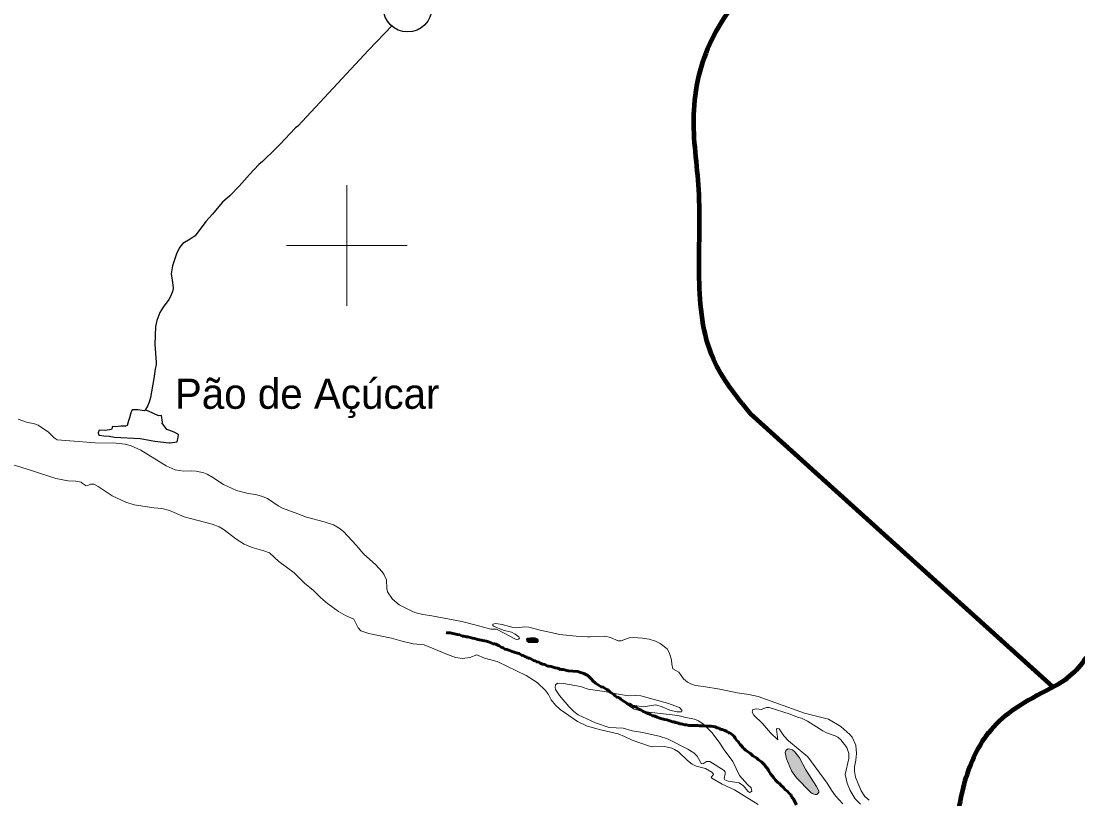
# Model space of a CAD drawing. Extents: x -1643653 to 4543381, y 1624270 to 13878484.
# Drawn here: x 669599 to 687117, y 8915829 to 8928718 of the extents above; entities that cross this region are included whole.
import ezdxf

# ---------------------------------------------------------------- set-up
doc = ezdxf.new("R2010")
doc.units = 0
doc.header["$LTSCALE"] = 200
doc.linetypes.add('LONG_DASH_SHORT_DASH', pattern=[9.9, 6, -1.2, 1.5, -1.2])
for name, color, linetype, lineweight in [('12', 7, 'Continuous', 25), ('2', 7, 'Continuous', 13), ('21', 7, 'Continuous', 25), ('23', 7, 'Continuous', 13), ('25', 7, 'Continuous', 13), ('48', 7, 'Continuous', 25), ('60', 7, 'Continuous', 13), ('7', 7, 'LONG_DASH_SHORT_DASH', 60), ('9', 7, 'Continuous', 90)]:
    doc.layers.add(name, color=color, linetype=linetype, lineweight=lineweight)
doc.layers.add('41', color=7, linetype='Continuous')

msp = doc.modelspace()

# ---------------------------------------------------------------- hatches: boundary and pattern name
at = {"layer": '25'}
for points in [[(678121.8, 8918499.9), (678099.7, 8918499.9), (678072.1, 8918499.9), (678038.9, 8918499.9), (677994.7, 8918494.3), (677978.1, 8918477.8), (677983.7, 8918444.6), (678016.8, 8918422.5), (678066.5, 8918422.5), (678116.3, 8918422.5), (678155, 8918422.5), (678171.5, 8918439.1), (678171.5, 8918466.7), (678155, 8918483.3)], [(682604.9, 8916312), (682500, 8916511.3), (682424.9, 8916610.1), (682387.8, 8916643), (682346.5, 8916655.7), (682313.7, 8916655.9), (682284.1, 8916639.2), (682267.8, 8916618.9), (682264.6, 8916598.1), (682286.2, 8916495.1), (682370.8, 8916295.4), (682452, 8916180.6), (682682.3, 8915939.4), (682710.5, 8915920.7), (682762.8, 8915903.1), (682787.5, 8915903.3), (682820.9, 8915934.7), (682822.2, 8915960.7), (682782.3, 8916035.7)]]:
    msp.add_hatch(color=256, dxfattribs=at).paths.add_polyline_path(points)

# ---------------------------------------------------------------- linework, layer by layer
at = {"layer": '12'}
for points in [[(675747.8, 8928644.7), (675357.8, 8928239.4), (674183.6, 8926978.8), (674145.1, 8926947.6), (673889.8, 8926674.1), (673817.5, 8926604.1)], [(673817.5, 8926604.1), (673601, 8926394.6), (673540.7, 8926341.3), (673385.9, 8926177.5), (673220, 8925987.8), (673060.2, 8925824.4), (672938.9, 8925717.3), (672905.6, 8925678)], [(672905.6, 8925678), (672769.2, 8925517), (672663.1, 8925399.6), (672486.7, 8925159.8), (672402.7, 8925104), (672277.3, 8925032.8), (672246.2, 8924995.7), (672220.2, 8924955.3), (672176.2, 8924860.7)], [(672176.2, 8924860.7), (672161.6, 8924829.2), (672110.6, 8924662), (672086.1, 8924531.1), (672095.5, 8924466.4)], [(672095.5, 8924466.4), (672118.8, 8924306.3), (672118.5, 8924278.5), (672104, 8924223.3), (672070.6, 8924145.4), (672047.1, 8924105), (671951.4, 8923978.3), (671897.8, 8923887.3), (671849.3, 8923755.3), (671827.1, 8923657.7), (671813, 8923357.8), (671840.2, 8923069), (671838.2, 8923027.3), (671822.3, 8922948), (671796.6, 8922795.7)], [(671796.6, 8922795.7), (671743.5, 8922481.6), (671721, 8922405.8), (671692.6, 8922335.7), (671657.6, 8922270.9)]]:
    msp.add_lwpolyline(points, dxfattribs=at)
at = {"layer": '2'}
for p, q in [((675000, 8924000), (675000, 8926000)), ((674000, 8925000), (676000, 8925000))]:
    msp.add_line(p, q, dxfattribs=at)
at = {"layer": '21'}
msp.add_lwpolyline([(672070.8, 8921729.3), (672183.6, 8921744.1), (672204.3, 8921823.7), (672205.8, 8921869.8), (672137.9, 8921906.6), (672045.5, 8921936.8), (672015.8, 8921950.8), (671951.1, 8922034), (671936.7, 8922041.8), (671940.3, 8922071), (671928.8, 8922182.7), (671874.6, 8922176.6), (671712.4, 8922251.7), (671659.2, 8922270.3), (671636.6, 8922261.5), (671534.1, 8922275.4), (671438.6, 8922277.6), (671419.5, 8922227.5), (671398.3, 8922143), (671378.3, 8922092.9), (671356.9, 8922015.4), (671328.1, 8922006.3), (671250.4, 8922007.9), (671162.4, 8921997.4), (671116.6, 8922002), (671109.5, 8921989.5), (671105, 8921961.4), (671096.8, 8921948), (670990.1, 8921931.4), (670891.9, 8921937.6), (670878.8, 8921896.3), (670882.6, 8921866.1), (670900, 8921857.8), (670970.5, 8921845.4), (671059.8, 8921839.3), (671147.8, 8921823.2), (671572.8, 8921799.1), (671817.6, 8921756.7), (672050.9, 8921730.4)], close=True, dxfattribs=at)
at = {"layer": '23'}
for points in [[(674185.8, 8920553), (673931.7, 8920649.3), (673860.5, 8920685.6), (673683.5, 8920804.3), (673583.2, 8920848.3), (673485, 8920874.1), (673363.4, 8920887.3), (673169, 8920938.3), (672954.4, 8921040.4), (672776.3, 8921157.4), (672681.9, 8921209.8), (672626.2, 8921231.8), (672503.5, 8921262.1), (672419, 8921266.9), (672299, 8921260.5), (672150.9, 8921284.8), (672004.6, 8921350.8), (671582.7, 8921606.9), (671424.1, 8921682), (671321.6, 8921707.8), (671173.4, 8921726.6), (670825.1, 8921729), (670198.9, 8921779.1), (670147.5, 8921810.8), (670051.3, 8921908.8), (669880.3, 8922022.2), (669805.2, 8922048.5), (669703.5, 8922065.4), (669551.5, 8922120.6)], [(674185.8, 8920553), (673931.7, 8920649.3), (673860.5, 8920685.6), (673683.5, 8920804.3), (673583.2, 8920848.3), (673485, 8920874.1), (673363.4, 8920887.3), (673169, 8920938.3), (672954.4, 8921040.4), (672776.3, 8921157.4), (672681.9, 8921209.8), (672626.2, 8921231.8), (672503.5, 8921262.1), (672419, 8921266.9), (672299, 8921260.5), (672150.9, 8921284.8), (672004.6, 8921350.8), (671582.7, 8921606.9), (671424.1, 8921682), (671321.6, 8921707.8), (671173.4, 8921726.6), (670825.1, 8921729), (670198.9, 8921779.1), (670147.5, 8921810.8), (670051.3, 8921908.8), (669880.3, 8922022.2), (669805.2, 8922048.5), (669703.5, 8922065.4), (669551.5, 8922120.6)], [(676406.6, 8918860.2), (676257.4, 8918887.3), (676128.1, 8918918.2), (676076.8, 8918937.9), (675867.5, 8919047.4), (675757.5, 8919139.9), (675675.3, 8919257.8), (675661.4, 8919317.4), (675656.7, 8919458.2), (675613.6, 8919553.2), (675585, 8919594.2), (675471.8, 8919715.9), (675278.2, 8919884.7), (675153.1, 8920035), (674944.3, 8920262), (674871.4, 8920317.9), (674779.7, 8920369.3), (674621.4, 8920420.9), (674331.2, 8920497.9), (674185.8, 8920553)], [(676406.6, 8918860.2), (676257.4, 8918887.3), (676128.1, 8918918.2), (676076.8, 8918937.9), (675867.5, 8919047.4), (675757.5, 8919139.9), (675675.3, 8919257.8), (675661.4, 8919317.4), (675656.7, 8919458.2), (675613.6, 8919553.2), (675585, 8919594.2), (675471.8, 8919715.9), (675278.2, 8919884.7), (675153.1, 8920035), (674944.3, 8920262), (674871.4, 8920317.9), (674779.7, 8920369.3), (674621.4, 8920420.9), (674331.2, 8920497.9), (674185.8, 8920553)], [(677144.9, 8918707), (676902.1, 8918770.1), (676406.6, 8918860.2)], [(677144.9, 8918707), (676902.1, 8918770.1), (676406.6, 8918860.2)], [(678458.3, 8918568.7), (678201.6, 8918623.4), (678015.6, 8918673.9), (677950.6, 8918679.4), (677809.8, 8918666), (677754.5, 8918668.8), (677573, 8918719.1), (677467.7, 8918734.3), (677419.8, 8918723.9), (677417.9, 8918704.6), (677431.5, 8918690.2), (677591, 8918627.5), (677728, 8918593.3), (677791.3, 8918560.8), (677847.1, 8918512.3), (677858.5, 8918492.6), (677846.8, 8918474.7), (677807.2, 8918472.7), (677479.7, 8918643.7), (677387.7, 8918643.9), (677144.9, 8918707)], [(678458.3, 8918568.7), (678201.6, 8918623.4), (678015.6, 8918673.9), (677950.6, 8918679.4), (677809.8, 8918666), (677754.5, 8918668.8), (677573, 8918719.1), (677467.7, 8918734.3), (677419.8, 8918723.9), (677417.9, 8918704.6), (677431.5, 8918690.2), (677591, 8918627.5), (677728, 8918593.3), (677791.3, 8918560.8), (677847.1, 8918512.3), (677858.5, 8918492.6), (677846.8, 8918474.7), (677807.2, 8918472.7), (677479.7, 8918643.7), (677387.7, 8918643.9), (677144.9, 8918707)], [(678989.1, 8918516.6), (678798.8, 8918527.6), (678523.8, 8918554.7), (678458.3, 8918568.7)], [(678989.1, 8918516.6), (678798.8, 8918527.6), (678523.8, 8918554.7), (678458.3, 8918568.7)], [(680908.5, 8917690.3), (680777.3, 8917710.3), (680703.4, 8917735.4), (680646.8, 8917765.9), (680579.7, 8917817.8), (680502.8, 8917929.2), (680402.5, 8917983.4), (680383.4, 8918063), (680379.9, 8918133), (680343.3, 8918257.1), (680305.8, 8918315.1), (680189.9, 8918405.5), (680113.5, 8918440.7), (680007.6, 8918474.6), (679902.1, 8918494.5), (679746.3, 8918505.8), (679679.3, 8918495.6), (679546, 8918450), (679498.9, 8918447.1), (679370.3, 8918504.3), (679274.2, 8918524.4), (679028.7, 8918514.3), (678989.1, 8918516.6)], [(680908.5, 8917690.3), (680777.3, 8917710.3), (680703.4, 8917735.4), (680646.8, 8917765.9), (680579.7, 8917817.8), (680502.8, 8917929.2), (680402.5, 8917983.4), (680383.4, 8918063), (680379.9, 8918133), (680343.3, 8918257.1), (680305.8, 8918315.1), (680189.9, 8918405.5), (680113.5, 8918440.7), (680007.6, 8918474.6), (679902.1, 8918494.5), (679746.3, 8918505.8), (679679.3, 8918495.6), (679546, 8918450), (679498.9, 8918447.1), (679370.3, 8918504.3), (679274.2, 8918524.4), (679028.7, 8918514.3), (678989.1, 8918516.6)], [(683658.1, 8915805.7), (683583.7, 8915866.4), (683521.7, 8915959.8), (683432.7, 8916191.5), (683413.5, 8916288.2), (683412.3, 8916362.4), (683436.2, 8916473.2), (683446.5, 8916578.6), (683438.1, 8916716.7), (683373.2, 8916850.2), (683336.3, 8916896.5), (683185, 8917028.5), (682980.6, 8917149.2), (682585, 8917249.1), (681819.1, 8917524), (681660.9, 8917561), (681466.4, 8917586.3), (681178.8, 8917648.9), (681178.8, 8917648.9), (680908.5, 8917690.3)], [(683658.1, 8915805.7), (683583.7, 8915866.4), (683521.7, 8915959.8), (683432.7, 8916191.5), (683413.5, 8916288.2), (683412.3, 8916362.4), (683436.2, 8916473.2), (683446.5, 8916578.6), (683438.1, 8916716.7), (683373.2, 8916850.2), (683336.3, 8916896.5), (683185, 8917028.5), (682980.6, 8917149.2), (682585, 8917249.1), (681819.1, 8917524), (681660.9, 8917561), (681466.4, 8917586.3), (681178.8, 8917648.9), (681178.8, 8917648.9), (680908.5, 8917690.3)]]:
    msp.add_lwpolyline(points, dxfattribs=at)
at = {"layer": '25'}
for points in [[(670613, 8921062.4), (670594.6, 8921075.1), (670505.7, 8921092.1), (670378.9, 8921097.7), (670172.5, 8921136.1), (669790.2, 8921268), (669181.6, 8921455.5), (668940.4, 8921522.2), (668553.3, 8921609.1), (668470.6, 8921646), (668322.8, 8921739.3), (667855.1, 8921816.8), (666980.9, 8921915.9), (665565.9, 8922078.1), (665402.5, 8922087.8), (665227.8, 8922071.5), (665027.5, 8922015.6), (664640.9, 8921845.5), (664531.1, 8921815.4)], [(669551.5, 8922120.6), (669703.5, 8922065.4), (669805.2, 8922048.5), (669880.3, 8922022.2), (670051.3, 8921908.8), (670147.5, 8921810.8), (670198.9, 8921779.1), (670825.1, 8921729), (671173.4, 8921726.6), (671321.6, 8921707.8), (671424.1, 8921682), (671582.7, 8921606.9), (672004.6, 8921350.8), (672150.9, 8921284.8), (672299, 8921260.5), (672419, 8921266.9), (672503.5, 8921262.1), (672626.2, 8921231.8), (672681.9, 8921209.8), (672776.3, 8921157.4), (672954.4, 8921040.4), (673169, 8920938.3), (673363.4, 8920887.3), (673485, 8920874.1), (673583.2, 8920848.3), (673683.5, 8920804.3), (673860.5, 8920685.6), (673931.7, 8920649.3), (674185.8, 8920553)], [(674298.5, 8919404.1), (674291.8, 8919409.6), (674126, 8919575.4), (673873, 8919765.1), (673715.5, 8919905.3), (673623, 8919941.7), (673428.6, 8919993.5), (673296.8, 8920049), (673159.2, 8920137.6), (672965, 8920287.3), (672880.8, 8920337.6), (672764.4, 8920379.9), (672301.8, 8920503.9), (672059.4, 8920609.5), (671934.4, 8920643.4), (671799.8, 8920650.2), (671472.2, 8920703.7), (671336.9, 8920745), (671109.4, 8920850.7), (670878.6, 8921005.6), (670802.7, 8921042.5), (670751.6, 8921047.3), (670704.9, 8921020.2), (670678.6, 8921017.5), (670613, 8921062.4)], [(674185.8, 8920553), (674331.2, 8920497.9), (674621.4, 8920420.9), (674779.7, 8920369.3), (674871.4, 8920317.9), (674944.3, 8920262), (675153.1, 8920035), (675278.2, 8919884.7), (675471.8, 8919715.9), (675585, 8919594.2), (675613.6, 8919553.2), (675656.7, 8919458.2), (675661.4, 8919317.4), (675675.3, 8919257.8), (675757.5, 8919139.9), (675867.5, 8919047.4), (676076.8, 8918937.9), (676128.1, 8918918.2), (676257.4, 8918887.3), (676406.6, 8918860.2)], [(681818.1, 8915736.8), (681425.2, 8915979.8), (681222.6, 8916074.7), (681046.9, 8916174.6), (681037.6, 8916191.5), (681077.1, 8916231.5), (681069.9, 8916251.6), (681048.6, 8916272.8), (680945.8, 8916329.8), (680790.6, 8916373.3), (680721.3, 8916405.2), (680645.7, 8916462.9), (680494.3, 8916609.8), (680432, 8916649.9), (680383.3, 8916669.5), (680263.9, 8916694.5), (680070.5, 8916694.2), (680014.4, 8916702), (679728.1, 8916803.7), (679599.7, 8916864.4), (679494.1, 8916904.4), (679183.1, 8916978), (678970.2, 8917037.8), (678820.7, 8917111.4), (678532.7, 8917311.3), (678456, 8917383.8), (678383.1, 8917469.9), (678338.7, 8917561.6), (678294.1, 8917624), (678150.8, 8917757.7), (677973.1, 8917871.9), (677487.9, 8918104.1), (677281.9, 8918159.9), (677153.7, 8918215.1), (677037.8, 8918171.3), (676918, 8918157), (676801.9, 8918174.5), (676667.5, 8918220.7), (676277.6, 8918381.7), (676099, 8918399.2), (675895.4, 8918446.5), (675739.5, 8918492.1), (675362.3, 8918567.1), (675228.4, 8918616), (675184.7, 8918661.3), (675115.9, 8918805.8), (674978.6, 8918869.4), (674860.2, 8918934.9), (674677.5, 8919067.2), (674567.5, 8919159.4), (674447.6, 8919281.5), (674298.5, 8919404.1)], [(676406.6, 8918860.2), (676902.1, 8918770.1), (677144.9, 8918707)], [(677144.9, 8918707), (677387.7, 8918643.9), (677479.7, 8918643.7), (677807.2, 8918472.7), (677846.8, 8918474.7), (677858.5, 8918492.6), (677847.1, 8918512.3), (677791.3, 8918560.8), (677728, 8918593.3), (677591, 8918627.5), (677431.5, 8918690.2), (677417.9, 8918704.6), (677419.8, 8918723.9), (677467.7, 8918734.3), (677573, 8918719.1), (677754.5, 8918668.8), (677809.8, 8918666), (677950.6, 8918679.4), (678015.6, 8918673.9), (678201.6, 8918623.4), (678458.3, 8918568.7)], [(678458.3, 8918568.7), (678523.8, 8918554.7), (678798.8, 8918527.6), (678989.1, 8918516.6)], [(678989.1, 8918516.6), (679028.7, 8918514.3), (679274.2, 8918524.4), (679370.3, 8918504.3), (679498.9, 8918447.1), (679546, 8918450), (679679.3, 8918495.6), (679746.3, 8918505.8), (679902.1, 8918494.5), (680007.6, 8918474.6), (680113.5, 8918440.7), (680189.9, 8918405.5), (680305.8, 8918315.1), (680343.3, 8918257.1), (680379.9, 8918133), (680383.4, 8918063), (680402.5, 8917983.4), (680502.8, 8917929.2), (680579.7, 8917817.8), (680646.8, 8917765.9), (680703.4, 8917735.4), (680777.3, 8917710.3), (680908.5, 8917690.3)], [(680908.5, 8917690.3), (681178.8, 8917648.9), (681178.8, 8917648.9), (681466.4, 8917586.3), (681660.9, 8917561), (681819.1, 8917524), (682585, 8917249.1), (682980.6, 8917149.2), (683185, 8917028.5), (683336.3, 8916896.5), (683373.2, 8916850.2), (683438.1, 8916716.7), (683446.5, 8916578.6), (683436.2, 8916473.2), (683412.3, 8916362.4), (683413.5, 8916288.2), (683432.7, 8916191.5), (683521.7, 8915959.8), (683583.7, 8915866.4), (683658.1, 8915805.7)], [(683514, 8915743.9), (683424.3, 8915831.4), (683340.7, 8915966.9), (683294.1, 8916091.3), (683261.6, 8916230.6), (683318.9, 8916497.7), (683318.9, 8916580.9), (683285.7, 8916678.7), (683188.7, 8916805.8), (683140.2, 8916850.4), (683094.9, 8916876.6), (682950.1, 8916924.1), (682886.8, 8916955.4), (682635, 8917119.5), (682537.5, 8917164.5), (682468.1, 8917183.6), (682346, 8917233.6), (681999.5, 8917342.7), (681956.9, 8917341.8), (681867.4, 8917308.4), (681794.8, 8917322), (681728.3, 8917312.8), (681716.4, 8917267.4), (681747.4, 8917215.7), (681890.3, 8917076.4), (682019, 8916922.4), (682142.9, 8916807.4), (682119.7, 8916983.6), (682130.7, 8916993.2), (682166.1, 8916989.6), (682243.8, 8916875.1), (682318.3, 8916790), (682638.3, 8916523.7), (682962.6, 8916089.6), (683031.4, 8915973.4), (683098.8, 8915878.5), (683218, 8915745.7)]]:
    msp.add_lwpolyline(points, dxfattribs=at)
for points in [[(678121.8, 8918499.9), (678099.7, 8918499.9), (678072.1, 8918499.9), (678038.9, 8918499.9), (677994.7, 8918494.3), (677978.1, 8918477.8), (677983.7, 8918444.6), (678016.8, 8918422.5), (678066.5, 8918422.5), (678116.3, 8918422.5), (678155, 8918422.5), (678171.5, 8918439.1), (678171.5, 8918466.7), (678155, 8918483.3)], [(681051.6, 8916931.9), (680917.2, 8917059.9), (680829.5, 8917121.2), (680764.3, 8917152.8), (680618.1, 8917176), (680486.7, 8917212.2), (679908, 8917275.5), (679762, 8917317), (679635.4, 8917396.8), (679910.2, 8917356.6), (680118, 8917385), (680224.5, 8917353.5), (680354.4, 8917300.2), (680468.1, 8917272.3), (680544.4, 8917273.7), (680558.6, 8917291.6), (680515, 8917345.8), (680314, 8917417.1), (679871.3, 8917537.1), (679776.1, 8917543.1), (679665.5, 8917539.2), (679433.9, 8917573.7), (679267.9, 8917609.1), (678996.5, 8917647.8), (678870.4, 8917690.1), (678589.1, 8917741.1), (678498, 8917744.3), (678469.7, 8917732.7), (678455.1, 8917717), (678451.8, 8917673.4), (678458.9, 8917639.2), (678523.3, 8917543), (678679.2, 8917360), (678761.9, 8917279.4), (678835.3, 8917221.6), (679118.2, 8917086.7), (679346.3, 8917013.9), (679576.6, 8917001.6), (679730.2, 8916958.4), (679899.8, 8916930.5), (680176.7, 8916871.1), (680311.5, 8916821.6), (680651, 8916653.5), (680752.3, 8916589.8), (680805.3, 8916538.2), (680876.6, 8916411.5), (680909.3, 8916413.3), (680957.8, 8916448.8), (681016.5, 8916451.2), (681252.3, 8916299.6), (681267.3, 8916278.3), (681272.5, 8916243.6), (681254.2, 8916164.9), (681262.6, 8916146.7), (681320.4, 8916124.1), (681503.1, 8916094), (681572.9, 8916043.7), (681643.2, 8915956.4), (681671.9, 8915935.7), (681689.5, 8915938.5), (681714.4, 8915957.7), (681702.9, 8916012.5), (681637.7, 8916065.1), (681506.7, 8916216.1), (681398.2, 8916446.9), (681252.7, 8916642.9), (681172.9, 8916771.4)], [(682604.9, 8916312), (682500, 8916511.3), (682424.9, 8916610.1), (682387.8, 8916643), (682346.5, 8916655.7), (682313.7, 8916655.9), (682284.1, 8916639.2), (682267.8, 8916618.9), (682264.6, 8916598.1), (682286.2, 8916495.1), (682370.8, 8916295.4), (682452, 8916180.6), (682682.3, 8915939.4), (682710.5, 8915920.7), (682762.8, 8915903.1), (682787.5, 8915903.3), (682820.9, 8915934.7), (682822.2, 8915960.7), (682782.3, 8916035.7)]]:
    msp.add_lwpolyline(points, close=True, dxfattribs=at)
at = {"layer": '48'}
msp.add_circle((676006.2, 8928939.6), 401.3, dxfattribs=at)
at = {"layer": '60', "lineweight": 25}
msp.add_spline([(814781, 9009175.5), (814787.2, 9009173.4), (814796.9, 9009173.4), (814799.4, 9009172.4), (814805.1, 9009174.5), (814805.6, 9009176.5), (814811.7, 9009179.5), (814811.7, 9009179.5), (814801.5, 9009181), (814790.7, 9009181.5), (814784.1, 9009183.1), (814777.4, 9009185.1), (814778.4, 9009175.5)], degree=3, dxfattribs=at)
at = {"layer": '7'}
for points in [[(677045, 8918504), (677001.7, 8918514.2), (676981.3, 8918516.8), (676940.6, 8918524.4), (676910.1, 8918524.4), (676869.4, 8918547.4), (676828.7, 8918555.1), (676714.1, 8918578.1), (676660.7, 8918583.2), (676646.3, 8918587.3)], [(679307.3, 8917640.1), (679279.3, 8917660.5), (679246.2, 8917678.4), (679213.1, 8917688.6), (679182.6, 8917709.1), (679152.1, 8917727), (679121.5, 8917747.4), (679075.7, 8917785.8), (679050.2, 8917819), (679024.8, 8917839.4), (678994.2, 8917872.7), (678958.6, 8917890.6), (678925.5, 8917908.4), (678892.5, 8917916.1), (678869.6, 8917923.8), (678826.3, 8917939.1), (678742.3, 8917946.8), (678666, 8917951.9), (678584.6, 8917972.3), (678538.8, 8917974.9), (678498, 8917992.8), (678452.2, 8918000.5), (678383.5, 8918020.9), (678347.9, 8918031.1), (678325, 8918031.1), (678279.2, 8918054.1), (678243.6, 8918059.2), (678202.8, 8918077.1), (678182.5, 8918092.5), (678149.4, 8918097.6), (678121.4, 8918118), (678093.4, 8918123.2), (678057.8, 8918143.6), (678029.8, 8918158.9), (677999.2, 8918158.9), (677981.4, 8918179.4), (677950.9, 8918189.6), (677920.4, 8918204.9), (677892.4, 8918212.6), (677856.7, 8918235.6), (677828.7, 8918243.3), (677790.6, 8918256.1), (677757.5, 8918263.7), (677737.1, 8918271.4), (677683.7, 8918294.4), (677653.2, 8918302.1), (677620.1, 8918309.7), (677592.1, 8918330.2), (677559, 8918345.5), (677525.9, 8918366), (677492.8, 8918381.3), (677467.4, 8918391.5), (677447, 8918396.7), (677419, 8918399.2), (677393.6, 8918417.1), (677365.6, 8918424.8), (677332.5, 8918435), (677312.1, 8918442.7), (677279.1, 8918450.3), (677225.6, 8918460.6), (677172.2, 8918470.8), (677151.8, 8918475.9), (677116.2, 8918486.1), (677080.6, 8918493.8), (677045, 8918504)], [(680338, 8917126.3), (680304.9, 8917136.5), (680271.8, 8917144.2), (680248.9, 8917149.3), (680218.4, 8917157), (680172.6, 8917174.9), (680142.1, 8917185.1), (680106.4, 8917197.9), (680086.1, 8917205.5), (680065.7, 8917208.1), (680032.6, 8917226), (680012.3, 8917236.2), (679986.8, 8917246.4), (679966.5, 8917254.1), (679935.9, 8917266.9), (679910.5, 8917277.1), (679882.5, 8917300.1), (679851.9, 8917310.3), (679816.3, 8917333.3), (679783.2, 8917353.8), (679757.8, 8917358.9), (679729.8, 8917364), (679704.3, 8917387), (679684, 8917397.2), (679663.6, 8917397.2), (679622.9, 8917425.3), (679594.9, 8917443.2), (679569.5, 8917461.1), (679541.5, 8917481.6), (679505.8, 8917509.7), (679475.3, 8917517.4), (679447.3, 8917537.8), (679421.8, 8917558.3), (679391.3, 8917578.7), (679363.3, 8917599.2), (679332.8, 8917632.4), (679307.3, 8917640.1)], [(682076.2, 8916175.4), (682050.8, 8916211.2), (682020.2, 8916241.9), (681987.1, 8916298.1), (681969.3, 8916331.4), (681936.2, 8916367.1), (681926, 8916387.6), (681895.5, 8916423.4), (681870, 8916443.8), (681836.9, 8916464.3), (681816.6, 8916482.2), (681793.7, 8916502.6), (681765.7, 8916520.5), (681730, 8916543.5), (681689.3, 8916581.9), (681663.9, 8916599.8), (681633.3, 8916620.2), (681605.3, 8916638.1), (681587.5, 8916658.5), (681564.6, 8916676.4), (681549.3, 8916696.9), (681521.3, 8916732.7), (681501, 8916753.1), (681483.1, 8916781.2), (681455.1, 8916801.7), (681434.8, 8916837.5), (681417, 8916870.7), (681368.6, 8916906.5), (681348.2, 8916921.8), (681320.2, 8916924.4), (681305, 8916944.8), (681266.8, 8916962.7), (681218.4, 8916978.1), (681190.5, 8916980.6), (681170.1, 8917001.1), (681139.6, 8917008.7), (681106.5, 8917024.1), (681073.4, 8917026.6), (681040.3, 8917036.8), (681014.9, 8917036.8), (680994.5, 8917036.8), (680958.9, 8917036.8), (680913.1, 8917041.9), (680877.5, 8917041.9), (680846.9, 8917041.9), (680816.4, 8917044.5), (680796, 8917044.5), (680765.5, 8917044.5), (680735, 8917044.5), (680714.6, 8917047.1), (680694.3, 8917047.1), (680673.9, 8917047.1), (680653.5, 8917052.2), (680623, 8917054.7), (680602.7, 8917057.3), (680564.5, 8917064.9), (680536.5, 8917072.6), (680516.1, 8917075.2), (680495.8, 8917082.8), (680475.4, 8917087.9), (680447.4, 8917093.1), (680427.1, 8917103.3), (680399.1, 8917108.4), (680368.5, 8917118.6), (680338, 8917126.3)], [(682450.4, 8915733.2), (682399.5, 8915838), (682371.5, 8915863.6), (682356.2, 8915899.4), (682328.2, 8915919.8), (682305.3, 8915958.2), (682262.1, 8915978.6), (682236.6, 8916016.9), (682201, 8916052.7), (682170.4, 8916086), (682142.4, 8916098.8), (682124.6, 8916119.2), (682106.8, 8916139.7), (682076.2, 8916175.4)]]:
    msp.add_lwpolyline(points, dxfattribs=at)
at = {"layer": '9'}
msp.add_line((686702.4, 8917687.5), (681689.3, 8922210.8), dxfattribs=at)
for points in [[(681689.3, 8922210.8), (681075.2, 8923117.8), (680840, 8924458.2), (680832.7, 8925926.8), (680750.4, 8927167), (681049, 8928410), (681805.8, 8929453.8), (682463.2, 8930066.4), (683146.5, 8930577.9), (683955, 8931444.8)], [(685563.3, 8914000.1), (685411.9, 8914186), (685156.8, 8914412), (685077.7, 8914993.8), (685249.9, 8916134.6), (685677.5, 8916973.4), (686082.1, 8917330.9), (686664.7, 8917664.4), (687019.1, 8917894.9), (687575, 8918481.4), (688360.8, 8918816.4), (688404.9, 8918868.1)]]:
    msp.add_spline(points, degree=3, dxfattribs=at)

# ---------------------------------------------------------------- texts
at = {"layer": '41'}
msp.add_text('Pão de Açúcar', height=500, dxfattribs=at).set_placement((672147.8, 8922293.7))

doc.saveas('drawing.dxf')
